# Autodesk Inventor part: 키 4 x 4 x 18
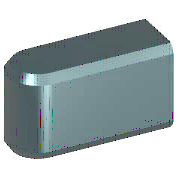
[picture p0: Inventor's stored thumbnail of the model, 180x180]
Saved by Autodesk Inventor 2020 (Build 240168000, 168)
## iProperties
Created: 2012-02
Part Number: 키 4 x 4 x 18
Material: 강철, 연강
Description: 키 및 해당 키홈
Document SubType Name: Modeling
Standard: KS B 1311
Designer: mduedu
Standards Organization: KS
Language: ko-KR
Size Designation: 4 x 4 x 18
Categories: <MemberInstance><Categories><Category DisplayName="샤프트 부품" InternalName="7f7aeb1f-a693-4053-b835-cee3144e0d98" Mnemonic="SHFT"><Category DisplayName="키" Interna
Density: 1 g/cm^3
Appearance: 밝은 황색
IsCustomPart: 1
Author: mduedu
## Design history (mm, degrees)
sketch "스케치1"
  geometry: L1 (2, 2)-(18, 2); L2 (18, 2)-(18, -2); L3 (18, -2)-(2, -2); L4 (0, 7)-(0, -7) reference; L5 (-5, 0)-(30, 0) reference; A1 r 2 centre (2, 0) between (2, 2) and (2, -2)
  constraints: 6 end point, 3 tangent, 2 point on circle, 1 centre point, 1 horizontal, 1 parallel, 1 perpendicular, 1 point on line
  dimensions: "d0" = 2 radius of A1 (= 0.5 x PB); "d7" = 18 distance between parallel lines of L2 L4 (= NLG)
workplane "Work Plane1"
workplane "Work Plane2"
extrude "본체1" new body sketch "스케치1" taper "d3" = 0 deg; stored distance "d4" = 10
workaxis "Work Axis1"
workplane "Work Plane4"
body "Solid1"
chamfer "모따기1" distance "d8" = 0.25 (= PHH); stored, may be unused: second distance "d9" = 0.25 (= PHH), angle "d13" = 45 deg
other parameters: "d1" = -2.5 (= -PNT), "d2" = 1.5 (= PH - PNT), "NLG" = 18 [user parameter; used in 2 equation terms], "PB" = 4 [user parameter; used in 1 equation term], "PNT" = 2.5 [user parameter; used in 2 equation terms], "PH" = 4 [user parameter; used in 1 equation term], "PHH" = 0.25 [user parameter; used in 2 equation terms], "d10" = 0, "d16" = 0, "d17" = 0, "d18" = 0, "RR" = 0.08 [user parameter], "WDMAX" = 12 [user parameter], "PLB1" = 18 (= NLG) [user parameter], "PUEB" = 1.8 [user parameter]
